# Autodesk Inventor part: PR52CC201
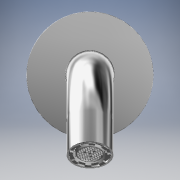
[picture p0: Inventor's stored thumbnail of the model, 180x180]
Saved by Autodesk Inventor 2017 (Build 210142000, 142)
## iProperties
Created: 2021-04
Part Number: PR52CC201
Material: Generico
Document SubType Name: Modeling
Designer: PIZZERA
Density: 1 g/cm^3
Appearance: Default
Author: PIZZERA
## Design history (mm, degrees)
feature "Base2"
node "Solido1"
node "Solido3"
